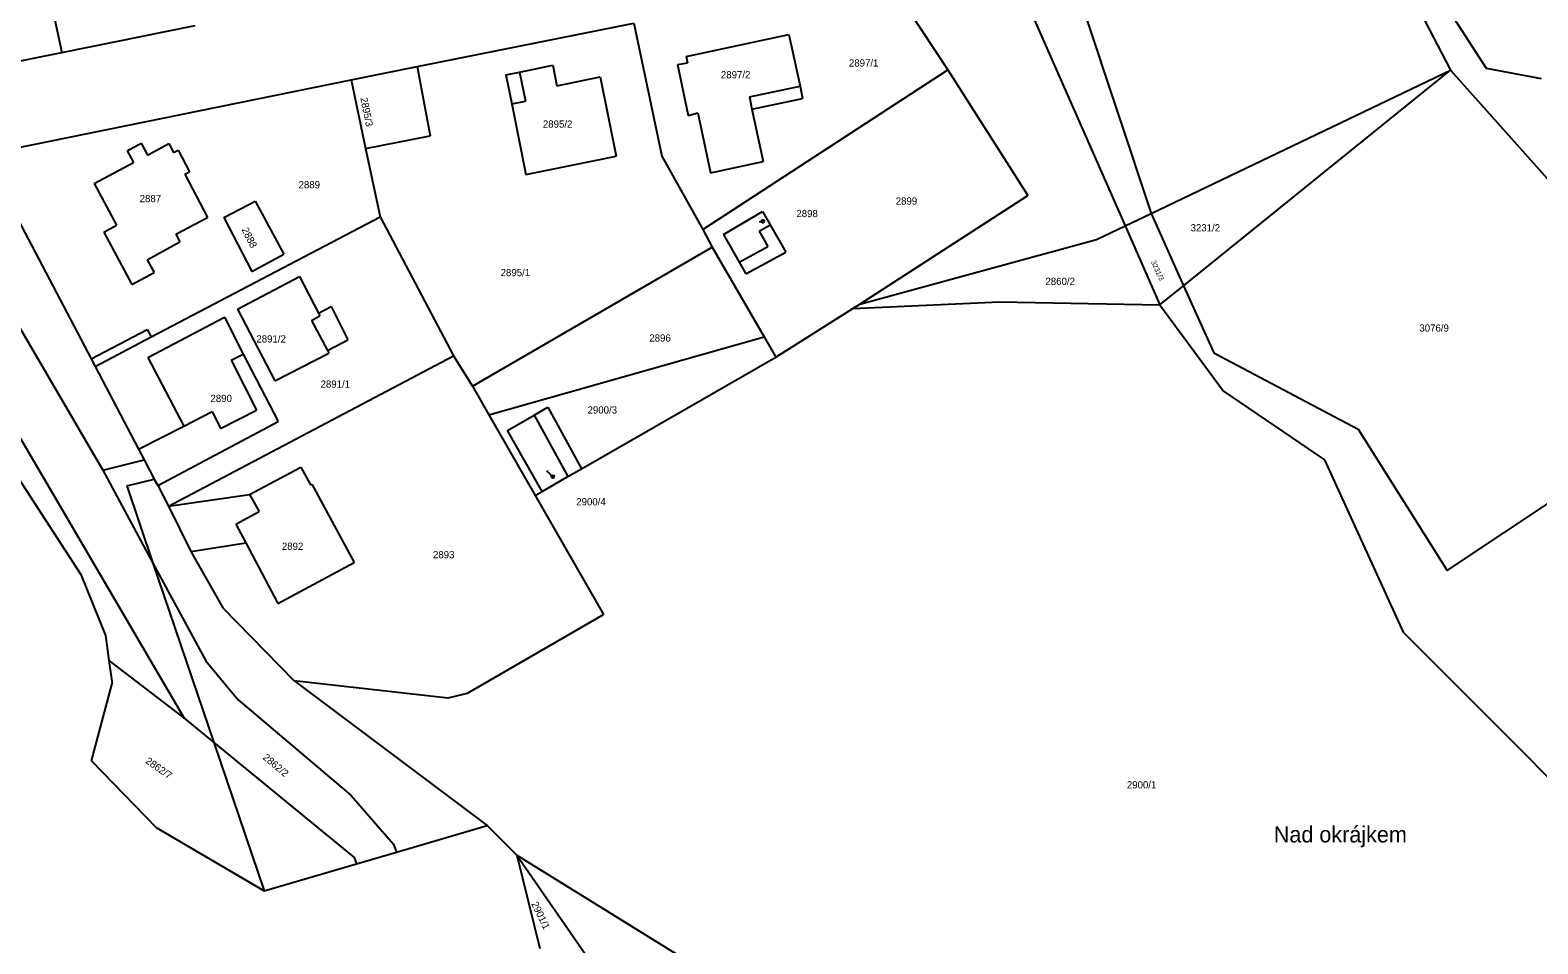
# Model space of a CAD drawing. Extents: x -722132 to -721608, y -1046877 to -1046449.
# Drawn here: x -721988.9 to -721811.3, y -1046720.6 to -1046613 of the extents above; entities that cross this region are included whole.
import ezdxf

# ---------------------------------------------------------------- set-up
doc = ezdxf.new("R2010")
doc.units = 0
for name, color, linetype in [('Vrstva 1', 7, 'Continuous'), ('Vrstva 15', 7, 'Continuous'), ('Vrstva 16', 7, 'Continuous'), ('Vrstva 18', 7, 'Continuous'), ('Vrstva 19', 7, 'Continuous'), ('Vrstva 4', 7, 'Continuous'), ('Vrstva 6', 7, 'Continuous')]:
    doc.layers.add(name, color=color, linetype=linetype)

msp = doc.modelspace()

# ---------------------------------------------------------------- linework, layer by layer
at = {"layer": 'Vrstva 1'}
for p, q in [((-721923.98, -1046664.67), (-721901.09, -1046651.53)), ((-721929.58, -1046658.36), (-721927.94, -1046657.42)), ((-721927.94, -1046657.42), (-721923.98, -1046664.67)), ((-721932.71, -1046660.15), (-721929.58, -1046658.36)), ((-721928.64, -1046667.35), (-721932.71, -1046660.15)), ((-721925.6, -1046665.6), (-721923.98, -1046664.67)), ((-721928.64, -1046667.35), (-721925.6, -1046665.6)), ((-721929.46, -1046667.82), (-721928.64, -1046667.35))]:
    msp.add_line(p, q, dxfattribs=at)
for points in [[(-721831.36, -1046595.92), (-721817.41, -1046617.52)], [(-721988.59, -1046600.03), (-721985.2, -1046615.68)], [(-721874.47, -1046603.13), (-721859.95, -1046636.08)], [(-721888.51, -1046606.08), (-721880.83, -1046617.73)], [(-721985.2, -1046615.68), (-721969.52, -1046612.5)], [(-721943.34, -1046617.33), (-721917.82, -1046612.2)], [(-721917.82, -1046612.2), (-721914.52, -1046627.86)], [(-721911.66, -1046616.13), (-721899.55, -1046613.57)], [(-721899.55, -1046613.57), (-721898.25, -1046619.62)], [(-722000.08, -1046618.64), (-721985.2, -1046615.68)], [(-721951.12, -1046618.9), (-721943.34, -1046617.33)], [(-721943.34, -1046617.33), (-721941.83, -1046625.47)], [(-721931.29, -1046617.97), (-721927.37, -1046617.18)], [(-721927.37, -1046617.18), (-721926.88, -1046619.58)], [(-721912.7, -1046617.08), (-721911.52, -1046616.88)], [(-721912.7, -1046617.08), (-721911.41, -1046623.08)], [(-721911.66, -1046616.13), (-721911.52, -1046616.88)], [(-721991.07, -1046627.03), (-721951.12, -1046618.9)], [(-721951.12, -1046618.9), (-721949.42, -1046626.96)], [(-721932.9, -1046618.29), (-721931.29, -1046617.97)], [(-721932.9, -1046618.29), (-721932.21, -1046621.72)], [(-721926.88, -1046619.58), (-721921.79, -1046618.55)], [(-721921.79, -1046618.55), (-721919.91, -1046627.88)], [(-721909.7, -1046636.5), (-721880.83, -1046617.73)], [(-721880.83, -1046617.73), (-721871.42, -1046632.51)], [(-721856.87, -1046634.61), (-721821.61, -1046617.74)], [(-721853.06, -1046643.12), (-721821.61, -1046617.74)], [(-721821.61, -1046617.74), (-721788.76, -1046654.57)], [(-721817.41, -1046617.52), (-721810.96, -1046618.75)], [(-722006.7, -1046619.85), (-721980.36, -1046664.85)], [(-721898.25, -1046619.62), (-721897.95, -1046621.07)], [(-721932.21, -1046621.72), (-721930.53, -1046630.04)], [(-721903.91, -1046622.33), (-721897.95, -1046621.07)], [(-721903.91, -1046622.33), (-721902.6, -1046628.52)], [(-721911.41, -1046623.08), (-721910.28, -1046622.78)], [(-721910.28, -1046622.78), (-721908.79, -1046629.84)], [(-721949.42, -1046626.96), (-721941.83, -1046625.47)], [(-721977.53, -1046627.23), (-721975.88, -1046626.34)], [(-721977.53, -1046627.23), (-721976.78, -1046628.62)], [(-721975.88, -1046626.34), (-721975.13, -1046627.74)], [(-721975.13, -1046627.74), (-721972.59, -1046626.37)], [(-721972.59, -1046626.37), (-721972.04, -1046627.44)], [(-721972.04, -1046627.44), (-721971.52, -1046627.17)], [(-721971.52, -1046627.17), (-721970.18, -1046629.71)], [(-721949.42, -1046626.96), (-721947.72, -1046635.01)], [(-721930.53, -1046630.04), (-721919.91, -1046627.88)], [(-721914.52, -1046627.86), (-721909.7, -1046636.5)], [(-721981.39, -1046631.1), (-721976.78, -1046628.62)], [(-721970.71, -1046629.99), (-721970.18, -1046629.71)], [(-721908.79, -1046629.84), (-721902.6, -1046628.52)], [(-721992.85, -1046630.66), (-721981.77, -1046651.73)], [(-721981.39, -1046631.1), (-721978.76, -1046635.99)], [(-721970.71, -1046629.99), (-721968.05, -1046635.11)], [(-721966.11, -1046635.1), (-721962.43, -1046633.16)], [(-721962.43, -1046633.16), (-721959.07, -1046639.43)], [(-721891.2, -1046645.3), (-721871.42, -1046632.51)], [(-721974.67, -1046649.14), (-721947.72, -1046635.01)], [(-721971.77, -1046637.06), (-721968.05, -1046635.11)], [(-721966.11, -1046635.1), (-721962.83, -1046641.44)], [(-721947.72, -1046635.01), (-721939.07, -1046651.37)], [(-721907.27, -1046637.08), (-721902.66, -1046634.37)], [(-721902.66, -1046634.37), (-721901.76, -1046635.94)], [(-721859.95, -1046636.08), (-721856.87, -1046634.61)], [(-721856.87, -1046634.61), (-721853.06, -1046643.12)], [(-721980.27, -1046636.81), (-721978.76, -1046635.99)], [(-721980.27, -1046636.81), (-721976.97, -1046643)], [(-721909.7, -1046636.5), (-721908.61, -1046638.6)], [(-721901.76, -1046635.94), (-721899.91, -1046639.16)], [(-721863.33, -1046637.7), (-721859.95, -1046636.08)], [(-721859.95, -1046636.08), (-721855.85, -1046645.38)], [(-721975.15, -1046640.08), (-721971.3, -1046637.96)], [(-721971.77, -1046637.06), (-721971.3, -1046637.96)], [(-721936.84, -1046654.96), (-721908.61, -1046638.6)], [(-721908.61, -1046638.6), (-721902.48, -1046649.15)], [(-721907.27, -1046637.08), (-721905.43, -1046640.36)], [(-721891.2, -1046645.3), (-721863.33, -1046637.7)], [(-721975.15, -1046640.08), (-721974.34, -1046641.55)], [(-721962.83, -1046641.44), (-721959.07, -1046639.43)], [(-721905.43, -1046640.36), (-721904.65, -1046641.74)], [(-721904.65, -1046641.74), (-721899.91, -1046639.16)], [(-721976.97, -1046643), (-721974.34, -1046641.55)], [(-721964.53, -1046645.89), (-721957.2, -1046642.05)], [(-721957.2, -1046642.05), (-721954.96, -1046646.36)], [(-721855.85, -1046645.38), (-721853.06, -1046643.12)], [(-721853.06, -1046643.12), (-721849.52, -1046651.02)], [(-721954.96, -1046646.36), (-721953.47, -1046645.56)], [(-721953.47, -1046645.56), (-721951.51, -1046649.51)], [(-721892.01, -1046645.82), (-721874.74, -1046645.04)], [(-721892.01, -1046645.82), (-721891.2, -1046645.3)], [(-721874.74, -1046645.04), (-721855.85, -1046645.38)], [(-721855.85, -1046645.38), (-721848.37, -1046655.55)], [(-721975.09, -1046651.59), (-721966.06, -1046646.82)], [(-721966.06, -1046646.82), (-721963.85, -1046651.18)], [(-721964.53, -1046645.89), (-721960.11, -1046654.32)], [(-721901.09, -1046651.53), (-721892.01, -1046645.82)], [(-721981.77, -1046651.73), (-721975.14, -1046648.26)], [(-721975.14, -1046648.26), (-721974.67, -1046649.14)], [(-721934.9, -1046658.34), (-721902.48, -1046649.15)], [(-721902.48, -1046649.15), (-721901.09, -1046651.53)], [(-721960.11, -1046654.32), (-721953.77, -1046651.06)], [(-721953.93, -1046650.75), (-721951.51, -1046649.51)], [(-721953.93, -1046650.75), (-721953.77, -1046651.06)], [(-721849.52, -1046651.02), (-721832.51, -1046660.01)], [(-721981.77, -1046651.73), (-721981.3, -1046652.62)], [(-721981.3, -1046652.62), (-721976.16, -1046662.38)], [(-721975.09, -1046651.59), (-721970.82, -1046659.64)], [(-721972.65, -1046669.06), (-721939.07, -1046651.37)], [(-721963.85, -1046651.18), (-721959.72, -1046659.12)], [(-721939.07, -1046651.37), (-721936.84, -1046654.96)], [(-721822.02, -1046676.63), (-721788.76, -1046654.57)], [(-721936.84, -1046654.96), (-721934.9, -1046658.34)], [(-721848.37, -1046655.55), (-721836.45, -1046663.63)], [(-721976.16, -1046662.38), (-721970.82, -1046659.64)], [(-721973.91, -1046666.66), (-721959.72, -1046659.12)], [(-721934.9, -1046658.34), (-721929.46, -1046667.82)], [(-721832.51, -1046660.01), (-721822.02, -1046676.63)], [(-721976.16, -1046662.38), (-721975.5, -1046663.64)], [(-721975.5, -1046663.64), (-721974.32, -1046665.9)], [(-721963.12, -1046667.69), (-721957.04, -1046664.47)], [(-721957.04, -1046664.47), (-721955.92, -1046666.56)], [(-721836.45, -1046663.63), (-721827.2, -1046683.92)], [(-721977.55, -1046666.68), (-721974.32, -1046665.9)], [(-721977.55, -1046666.68), (-721974.47, -1046675.77)], [(-721974.32, -1046665.9), (-721973.91, -1046666.66)], [(-721973.91, -1046666.66), (-721972.65, -1046669.06)], [(-721955.92, -1046666.56), (-721955.75, -1046666.47)], [(-721955.75, -1046666.47), (-721950.79, -1046675.69)], [(-721972.65, -1046669.06), (-721963.12, -1046667.69)], [(-721929.46, -1046667.82), (-721921.4, -1046681.84)], [(-721972.65, -1046669.06), (-721970.03, -1046674.4)], [(-721970.03, -1046674.4), (-721963.55, -1046673.41)], [(-721963.55, -1046673.41), (-721959.76, -1046680.52)], [(-721974.47, -1046675.77), (-721967.32, -1046696.88)], [(-721970.03, -1046674.4), (-721966.25, -1046681.04)], [(-721959.76, -1046680.52), (-721950.79, -1046675.69)], [(-721966.25, -1046681.04), (-721957.86, -1046689.61)], [(-721937.41, -1046691.1), (-721921.4, -1046681.84)], [(-721827.2, -1046683.92), (-721796.01, -1046715.1)], [(-721957.86, -1046689.61), (-721939.71, -1046691.64)], [(-721957.86, -1046689.61), (-721935.1, -1046706.68)], [(-721939.71, -1046691.64), (-721937.41, -1046691.1)], [(-721970.8, -1046694.03), (-721967.32, -1046696.88)], [(-721967.32, -1046696.88), (-721961.39, -1046714.37)], [(-721945.77, -1046709.8), (-721935.1, -1046706.68)], [(-721935.1, -1046706.68), (-721931.6, -1046710.14)], [(-721961.39, -1046714.37), (-721950.51, -1046711.19)], [(-721950.51, -1046711.19), (-721945.77, -1046709.8)], [(-721931.6, -1046710.14), (-721855.63, -1046757.17)]]:
    msp.add_lwpolyline(points, dxfattribs=at)
at = {"layer": 'Vrstva 16'}
for points in [[(-721903.03, -1046635.59), (-721902.64, -1046635.53)], [(-721928.1, -1046664.93), (-721927.37, -1046665.6)]]:
    msp.add_lwpolyline(points, dxfattribs=at)
for centre in [(-721902.64, -1046635.53), (-721927.37, -1046665.6)]:
    msp.add_circle(centre, 0.175, dxfattribs=at)
at = {"layer": 'Vrstva 4'}
msp.add_line((-721929.58, -1046658.36), (-721925.6, -1046665.6), dxfattribs=at)
for points in [[(-721931.29, -1046617.97), (-721930.59, -1046621.39)], [(-721904.21, -1046620.88), (-721898.25, -1046619.62)], [(-721904.21, -1046620.88), (-721903.91, -1046622.33)], [(-721932.21, -1046621.72), (-721930.59, -1046621.39)], [(-722010.47, -1046626.38), (-721970.8, -1046694.03)], [(-721903.08, -1046636.69), (-721901.76, -1046635.94)], [(-721903.08, -1046636.69), (-721902.06, -1046638.5)], [(-721905.43, -1046640.36), (-721902.06, -1046638.5)], [(-721955.78, -1046647.23), (-721954.81, -1046646.66)], [(-721955.78, -1046647.23), (-721953.93, -1046650.75)], [(-721954.96, -1046646.36), (-721954.81, -1046646.66)], [(-721981.3, -1046652.62), (-721974.67, -1046649.14)], [(-721965.26, -1046651.89), (-721963.85, -1046651.18)], [(-721965.26, -1046651.89), (-721962.28, -1046657.76)], [(-721970.82, -1046659.64), (-721967.51, -1046657.94)], [(-721967.51, -1046657.94), (-721966.5, -1046659.93)], [(-721966.5, -1046659.93), (-721962.28, -1046657.76)], [(-721980.36, -1046664.85), (-721974.47, -1046675.77)], [(-721963.12, -1046667.69), (-721961.97, -1046669.72)], [(-721964.72, -1046671.2), (-721961.97, -1046669.72)], [(-721964.72, -1046671.2), (-721963.55, -1046673.41)], [(-721974.47, -1046675.77), (-721968.26, -1046687.28)], [(-721968.26, -1046687.28), (-721964.43, -1046691.89)], [(-721964.43, -1046691.89), (-721951.14, -1046703.15)], [(-721967.32, -1046696.88), (-721950.77, -1046710.43)], [(-721951.14, -1046703.15), (-721946.12, -1046708.87)], [(-721946.12, -1046708.87), (-721945.77, -1046709.8)], [(-721950.77, -1046710.43), (-721950.51, -1046711.19)]]:
    msp.add_lwpolyline(points, dxfattribs=at)
at = {"layer": 'Vrstva 6'}
for points in [[(-721846.82, -1046569.29), (-721821.61, -1046617.74)], [(-721876.68, -1046575.04), (-721856.87, -1046634.61)], [(-721980.36, -1046664.85), (-721975.5, -1046663.64)], [(-721990.34, -1046665.74), (-721982.96, -1046677.13)], [(-721982.96, -1046677.13), (-721980.07, -1046684.3)], [(-721980.07, -1046684.3), (-721979.66, -1046687.26)], [(-721979.66, -1046687.26), (-721970.8, -1046694.03)], [(-721979.66, -1046687.26), (-721979.28, -1046689.95)], [(-721981.72, -1046699.06), (-721979.28, -1046689.95)], [(-721981.72, -1046699.06), (-721974.08, -1046706.91)], [(-721974.08, -1046706.91), (-721961.39, -1046714.37)], [(-721931.6, -1046710.14), (-721928.89, -1046721.13)], [(-721931.6, -1046710.14), (-721922.86, -1046722.8)]]:
    msp.add_lwpolyline(points, dxfattribs=at)

# ---------------------------------------------------------------- texts
at = {"layer": 'Vrstva 15'}
msp.add_text('Nad okrájkem', height=1.9, dxfattribs=at).set_placement((-721842.44, -1046708.66))
at = {"layer": 'Vrstva 16'}
for s, p in [('2898', (-721898.68, -1046635.05)), ('2900/4', (-721924.61, -1046668.98))]:
    msp.add_text(s, height=0.85, dxfattribs=at).set_placement(p)
at = {"layer": 'Vrstva 18'}
for s, p in [('2897/1', (-721892.49, -1046617.33)), ('2889', (-721957.32, -1046631.66)), ('2899', (-721886.98, -1046633.58)), ('3231/2', (-721852.24, -1046636.73)), ('2895/1', (-721933.52, -1046642)), ('2860/2', (-721869.34, -1046643.04)), ('2896', (-721916, -1046649.7)), ('3076/9', (-721825.29, -1046648.53)), ('2891/1', (-721954.73, -1046655.13)), ('2900/3', (-721923.28, -1046658.17)), ('2893', (-721941.49, -1046675.21)), ('2900/1', (-721859.75, -1046702.3))]:
    msp.add_text(s, height=0.85, dxfattribs=at).set_placement(p)
for s, height, rotation, p in [('3231/3', 0.595, 294.2772, (-721856.92, -1046640.31)), ('2862/7', 0.85, 324.8456, (-721975.44, -1046699.25)), ('2862/2', 0.85, 319.9074, (-721961.6, -1046698.78)), ('2901/1', 0.85, 295.7127, (-721929.93, -1046715.87))]:
    msp.add_text(s, height=height, rotation=rotation, dxfattribs=at).set_placement(p)
at = {"layer": 'Vrstva 19'}
for s, height, p in [('2897/2', 0.85, (-721907.57, -1046618.71)), ('2895/2', 0.85, (-721928.54, -1046624.52)), ('2887', 0.85, (-721976.04, -1046633.29)), ('2891/2', 0.85, (-721962.29, -1046649.81)), ('2890', 0.85, (-721967.7, -1046656.81)), ('2900/4', 0.1, (-721928.1, -1046664.93)), ('2892', 0.85, (-721959.29, -1046674.22))]:
    msp.add_text(s, height=height, dxfattribs=at).set_placement(p)
for s, height, rotation, p in [('2895/3', 0.85, 281.3827, (-721950.05, -1046621.04)), ('2888', 0.85, 296.5385, (-721964.05, -1046636.52)), ('2898', 0.1, 0.3529, (-721903.18, -1046635.59))]:
    msp.add_text(s, height=height, rotation=rotation, dxfattribs=at).set_placement(p)

doc.saveas('drawing.dxf')
